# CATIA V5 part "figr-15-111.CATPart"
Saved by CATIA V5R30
Part number: Part1
Bounding box of the stored display mesh (mm): x 0.737 to 206.429, y 0 to 112.04, z -6 to 2
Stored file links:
  D:\PROJECTS\CATIA V56R 2020\Resources\Parts File\c15_catia_v5_6r2020_prt\figr-15-111.CATPart
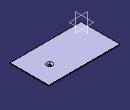
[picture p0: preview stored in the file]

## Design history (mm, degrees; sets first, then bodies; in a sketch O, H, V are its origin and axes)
SheetMetalParameters1: Thickness 2, BendRadius 4, KFactor 0.400515 {= log(min(100,max(20*SheetMetalParameters1.BendRadius,SheetMetalParameters1.Thickness)/SheetMetalParameters1.Thickness))/log(100)/2}, ReliefRadialLength 1, ReliefAxialLength 2, MinimumBendRadius 0
Body1 (main body)
  Sketch1 on xy-plane, origin (0, 0, 0), H (1, 0, 0), V (0, 1, 0)
    line L1 (0.7372, 112.0403) -> (206.4285, 112.0403)
    line L2 (206.4285, 112.0403) -> (206.4285, 0)
    line L3 (206.4285, 0) -> (0.7372, 0)
    line L4 (0.7372, 0) -> (0.7372, 112.0403)
    horizontal: L1 H, L3 H
    vertical: L2 V, L4 V
  Wall1: Thickness 2, Profile Sketch1, OffsetValue 0
  Sketch2 on face of Wall1, origin (152.409, 60.7083, 2), H (1, 0, 0), V (0, 1, 0)
    point P1 (0, 0)
  d_Stamp1: KFacteur 0.400515 {= SheetMetalParameters1.KFactor}, NewRoot_AttribNormalisation "No Standard", Stamp_FilletActivity true, Stamp_FilletRadius 2, Stamp_IntersectFilletRadius 2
